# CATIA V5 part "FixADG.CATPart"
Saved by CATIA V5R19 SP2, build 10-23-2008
Part number: FixADG
Bounding box of the stored display mesh (mm): x -28 to 10, y -5 to 65, z 85 to 181.213
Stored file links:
  D:\France\IFMA\IAO\Projet\FixADG.CATPart
  D:\France\IFMA\IAO\Projet\pruangdaja_CAO.CATProduct
  D:\France\IFMA\IAO\Projet\SquelettePrin.CATPart
  D:\France\IFMA\IAO\Projet\SqueletteBCD.CATPart
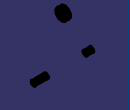
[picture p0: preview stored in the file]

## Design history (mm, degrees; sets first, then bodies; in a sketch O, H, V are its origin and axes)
External parameters (linked from other documents)
  External.Largeur = 10 mm
  External.RayonTrou = 5 mm
  External.RayonTrouBCD = 5 mm
Set1
  Point1 to Point3: linked copy from another document
  Plane1: linked copy from another document
Set2
  Plane2: type OffsetPt, RefPlane Plane1, RefPoint Point1
  Sketch1 on Plane2, origin (0, 0, 0), H (0, 1, 0), V (0, 0, 1)
    circle A1 centre (0, 90) radius 5
    point P1 (0, 90)
    reference projected point E1 (0, 90) from Point1
    radius A1 = 5 {= External.RayonTrou}
    coincidence: P1 V, P1 E1
  Plane3: type OffsetPt, RefPlane Plane1, RefPoint Point2
  Sketch2 on Plane3, origin (0, 0, 0), H (0, 1, 0), V (0, 0, 1)
    circle A1 centre (60, 150) radius 5
    point P1 (60, 150)
    reference projected point E1 (60, 150) from Point2
    radius A1 = 5 {= External.RayonTrouBCD}
    coincidence: P1 E1
  Plane4: type OffsetPt, RefPlane Plane1, RefPoint Point3
  Sketch3 on Plane4, origin (0, 0, 0), H (0, 1, 0), V (0, 0, 1)
    circle A1 centre (11.2132, 171.2132) radius 5
    point P1 (11.2132, 171.2132)
    circle A2 centre (11.2132, 171.2132) radius 10
    reference projected point E1 (11.2132, 171.2132) from Point3
    radius A1 = 5 {= External.RayonTrou}
    radius A2 = 10 {= External.RayonTrou *2}
    coincidence: P1 E1
Body1 (main body)
  Pad1: profile Sketch1, direction (1, 0, 0), length 10 {= External.Largeur}, mirrored extent
  Pad2: profile Sketch2, direction (-1, 0, 0), length 20, opposite side length -10
  Pad3: profile Sketch3, direction (-1, 0, 0), length 28, opposite side length -22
